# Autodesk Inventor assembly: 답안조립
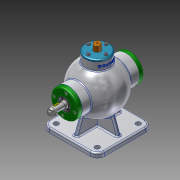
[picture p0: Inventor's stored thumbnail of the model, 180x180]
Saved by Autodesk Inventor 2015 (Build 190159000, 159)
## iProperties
Created: 2025-08
Part Number: 답안조립
Document SubType Name: Assembly
Designer: USER
Author: USER
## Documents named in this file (15)
- C:\Users\USER\Desktop\750808V1004\답안조립.iam
- C:\Users\USER\Desktop\750808V1004\본체.ipt
- C:\Users\USER\Desktop\750808V1004\가져온 구성요소\V-벨트풀리\V-벨트풀리.ipt
- C:\Users\USER\Desktop\750808V1004\가져온 구성요소\너트 M8\너트 M8.ipt
- C:\Users\USER\Desktop\750808V1004\가져온 구성요소\뒤커버\뒤커버.ipt
- C:\Users\USER\Desktop\750808V1004\가져온 구성요소\베어링- 6202\베어링- 6202.ipt
- C:\Users\USER\Desktop\750808V1004\가져온 구성요소\볼트 M4 x 12\볼트 M4 x 12.ipt
- C:\Users\USER\Desktop\750808V1004\가져온 구성요소\볼트 M4 x 16\볼트 M4 x 16.ipt
- C:\Users\USER\Desktop\750808V1004\가져온 구성요소\상부커버\상부커버.ipt
- C:\Users\USER\Desktop\750808V1004\가져온 구성요소\슬라이드\슬라이드.ipt
- C:\Users\USER\Desktop\750808V1004\가져온 구성요소\앞커버\앞커버.ipt
- C:\Users\USER\Desktop\750808V1004\가져온 구성요소\오일실 15 30 7\오일실 15 30 7.ipt
- C:\Users\USER\Desktop\750808V1004\가져온 구성요소\칼라\칼라.ipt
- C:\Users\USER\Desktop\750808V1004\가져온 구성요소\키 4 x 4 x 12\키 4 x 4 x 12.ipt
- C:\Users\USER\Desktop\750808V1004\가져온 구성요소\편심축\편심축.ipt
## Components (1 placed, 1 different names)
1. V-벨트풀리:1
